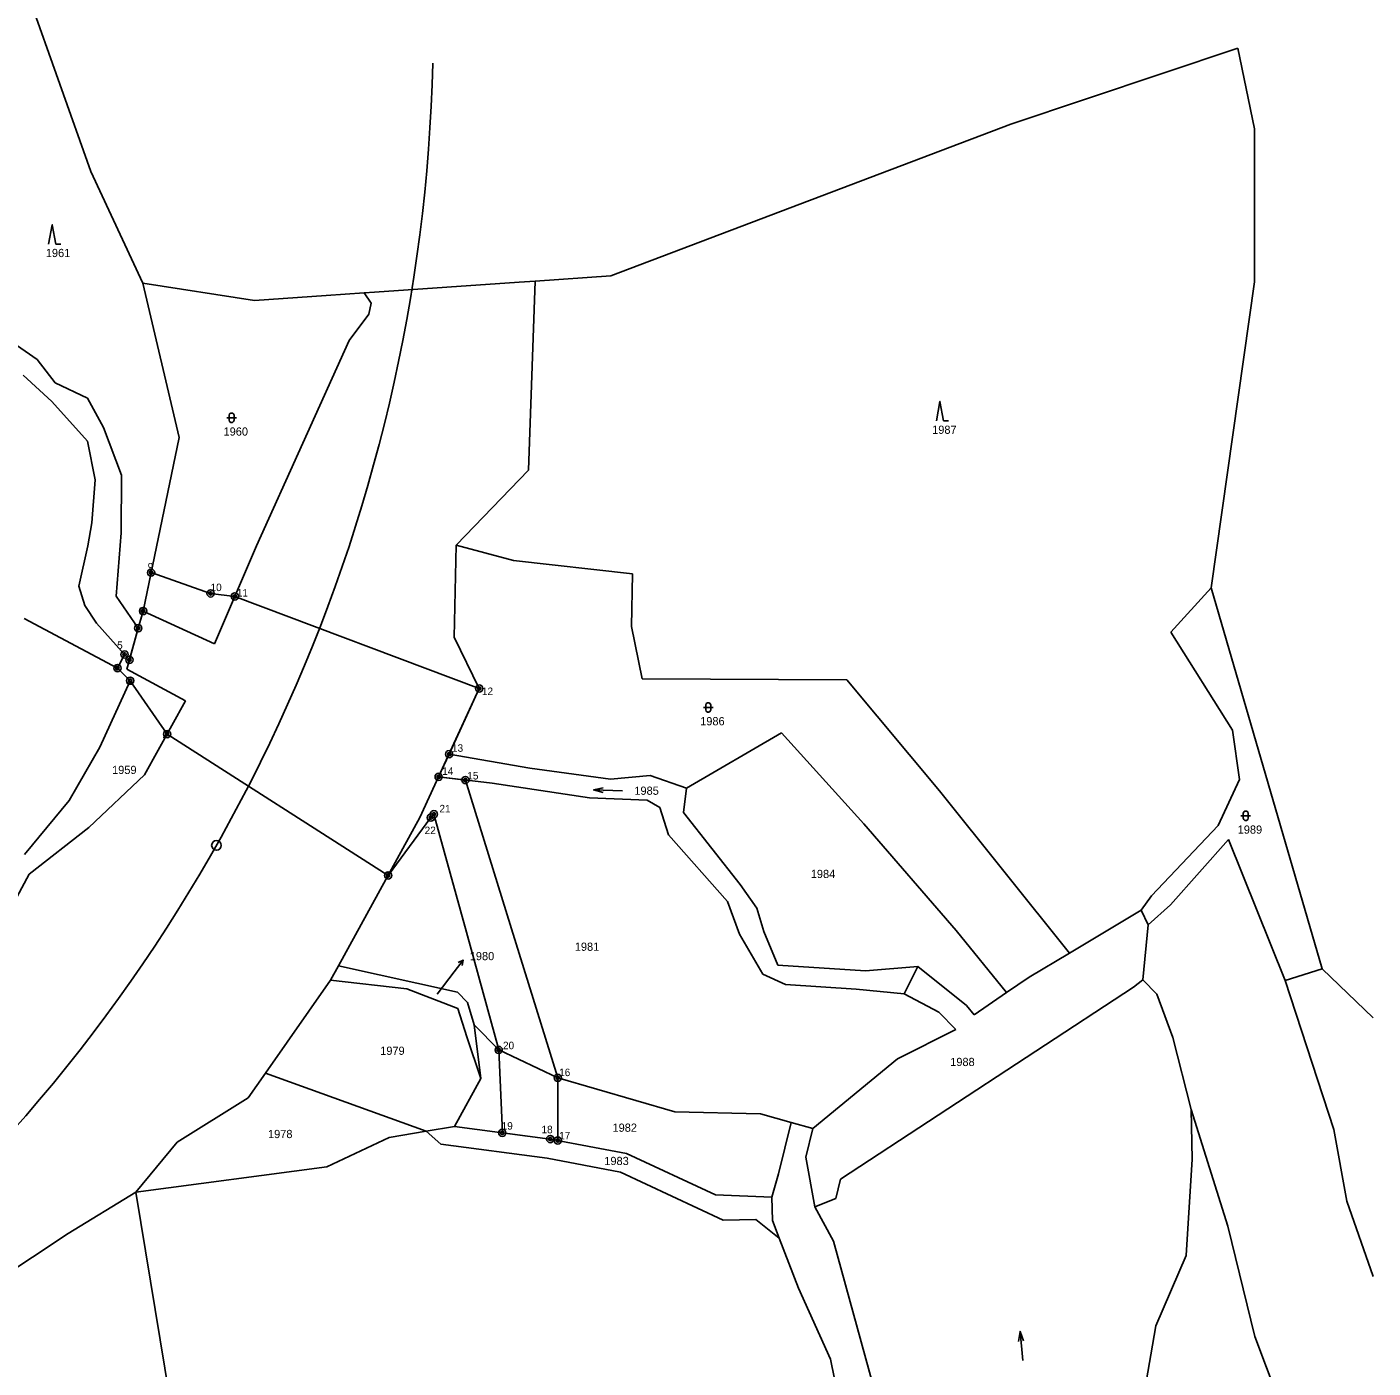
# Model space of a CAD drawing. Extents: x -801853 to -800578, y -1017479 to -1016338.
# Drawn here: x -801170.2 to -800891.7, y -1017184.4 to -1016906.9 of the extents above; entities that cross this region are included whole.
import ezdxf

# ---------------------------------------------------------------- set-up
doc = ezdxf.new("R2010")
doc.units = 0
for name, color, linetype in [('body', 7, 'Continuous'), ('cisla', 7, 'Continuous'), ('Default', 7, 'Continuous'), ('KN_HRANICE', 7, 'Continuous'), ('KN_KULTURY', 7, 'Continuous'), ('KN_PARCELY', 7, 'Continuous'), ('obvod_stavby', 7, 'Continuous'), ('Svršek_hkm_100', 7, 'Continuous'), ('Železniční svršek', 7, 'Continuous')]:
    doc.layers.add(name, color=color, linetype=linetype)

# ---------------------------------------------------------------- blocks, each defined once
blk = doc.blocks.new('308')
at = {"layer": 'Default'}
blk.add_lwpolyline([(-0.75, 0), (0, 4), (0.75, 0), (1.75, 0)], dxfattribs=at)
blk = doc.blocks.new('316')
at = {"layer": 'Default'}
for points in [[(-1, 1), (0.27, 1), (1, 1)], [(-0.5, 1.5), (-0.4, 1.79), (-0.15, 1.97), (0.16, 1.97), (0.41, 1.79), (0.51, 1.5), (0.51, 0.5), (0.41, 0.21), (0.16, 0.03), (-0.15, 0.03), (-0.4, 0.21), (-0.5, 0.5), (-0.5, 1.5)]]:
    blk.add_lwpolyline(points, dxfattribs=at)
blk = doc.blocks.new('802')
at = {"layer": 'Default'}
blk.add_line((-3, 0), (3, 0), dxfattribs=at)
blk.add_lwpolyline([(1, 0.5), (3, 0), (1, -0.5)], dxfattribs=at)
blk = doc.blocks.new('10292')
at = {"layer": 'Default'}
blk.add_line((0, 3), (0, 0), dxfattribs=at)
blk.add_lwpolyline([(-0.5, 2), (0, 3), (0.5, 2)], dxfattribs=at)

msp = doc.modelspace()

# ---------------------------------------------------------------- linework, layer by layer
at = {"layer": 'body'}
for p, q in [((-801144.52, -1017019.83), (-801144.52, -1017019.83)), ((-801132.21, -1017024.12), (-801132.21, -1017024.12)), ((-801127.2, -1017024.74), (-801127.2, -1017024.74)), ((-801146.17, -1017027.77), (-801146.17, -1017027.77)), ((-801147.17, -1017031.33), (-801147.17, -1017031.33)), ((-801150, -1017036.76), (-801150, -1017036.76)), ((-801151.48, -1017039.58), (-801151.48, -1017039.58)), ((-801149.01, -1017037.86), (-801149.01, -1017037.86)), ((-801148.85, -1017042.19), (-801148.85, -1017042.19)), ((-801076.63, -1017043.81), (-801076.63, -1017043.81)), ((-801141.22, -1017053.25), (-801141.22, -1017053.25)), ((-801082.88, -1017057.4), (-801082.88, -1017057.4)), ((-801085.03, -1017062.08), (-801085.03, -1017062.08)), ((-801079.49, -1017062.75), (-801079.49, -1017062.75)), ((-801086.64, -1017070.52), (-801086.64, -1017070.52)), ((-801086, -1017069.82), (-801086, -1017069.82)), ((-801095.48, -1017082.49), (-801095.48, -1017082.49)), ((-801072.61, -1017118.61), (-801072.61, -1017118.61)), ((-801060.39, -1017124.37), (-801060.39, -1017124.37)), ((-801071.86, -1017135.76), (-801071.86, -1017135.76)), ((-801061.94, -1017137.05), (-801061.94, -1017137.05)), ((-801060.39, -1017137.35), (-801060.39, -1017137.35))]:
    msp.add_line(p, q, dxfattribs=at)
for centre, radius in [((-801144.52, -1017019.83), 0.75), ((-801144.52, -1017019.83), 0.35), ((-801132.21, -1017024.12), 0.75), ((-801132.21, -1017024.12), 0.35), ((-801127.2, -1017024.74), 0.75), ((-801127.2, -1017024.74), 0.35), ((-801146.17, -1017027.77), 0.75), ((-801146.17, -1017027.77), 0.35), ((-801147.17, -1017031.33), 0.75), ((-801147.17, -1017031.33), 0.35), ((-801150, -1017036.76), 0.75), ((-801150, -1017036.76), 0.35), ((-801149.01, -1017037.86), 0.75), ((-801151.48, -1017039.58), 0.75), ((-801151.48, -1017039.58), 0.35), ((-801149.01, -1017037.86), 0.35), ((-801148.85, -1017042.19), 0.75), ((-801148.85, -1017042.19), 0.35), ((-801076.63, -1017043.81), 0.75), ((-801076.63, -1017043.81), 0.35), ((-801141.22, -1017053.25), 0.75), ((-801141.22, -1017053.25), 0.35), ((-801082.88, -1017057.4), 0.75), ((-801082.88, -1017057.4), 0.35), ((-801085.03, -1017062.08), 0.75), ((-801085.03, -1017062.08), 0.35), ((-801079.49, -1017062.75), 0.75), ((-801079.49, -1017062.75), 0.35), ((-801086.64, -1017070.52), 0.75), ((-801086.64, -1017070.52), 0.35), ((-801086, -1017069.82), 0.75), ((-801086, -1017069.82), 0.35), ((-801095.48, -1017082.49), 0.75), ((-801095.48, -1017082.49), 0.35), ((-801072.61, -1017118.61), 0.75), ((-801072.61, -1017118.61), 0.35), ((-801060.39, -1017124.37), 0.75), ((-801060.39, -1017124.37), 0.35), ((-801071.86, -1017135.76), 0.75), ((-801071.86, -1017135.76), 0.35), ((-801061.94, -1017137.05), 0.75), ((-801061.94, -1017137.05), 0.35), ((-801060.39, -1017137.35), 0.75), ((-801060.39, -1017137.35), 0.35)]:
    msp.add_circle(centre, radius, dxfattribs=at)
at = {"layer": 'KN_HRANICE'}
for p, q in [((-801173.56, -1016890), (-801157.02, -1016936.79)), ((-800966.67, -1016927.02), (-800919.72, -1016911.28)), ((-800919.72, -1016911.28), (-800916.22, -1016927.99)), ((-801049.4, -1016958.4), (-800966.67, -1016927.02)), ((-800916.22, -1016927.99), (-800916.27, -1016959.63)), ((-801157.02, -1016936.79), (-801146.24, -1016959.95)), ((-801068.35, -1016959.71), (-801065.05, -1016959.48)), ((-801066.45, -1016998.62), (-801065.05, -1016959.48)), ((-801065.05, -1016959.48), (-801049.4, -1016958.4)), ((-801138.7, -1016991.88), (-801146.24, -1016959.95)), ((-801146.24, -1016959.95), (-801123.1, -1016963.5)), ((-801108.28, -1016962.47), (-801100.45, -1016961.93)), ((-801100.45, -1016961.93), (-801098.33, -1016961.78)), ((-801099.01, -1016964.03), (-801100.45, -1016961.93)), ((-801098.33, -1016961.78), (-801068.35, -1016959.71)), ((-800916.27, -1016959.63), (-800925.21, -1017022.97)), ((-801123.1, -1016963.5), (-801108.28, -1016962.47)), ((-801099.44, -1016966.34), (-801099.01, -1016964.03)), ((-801103.54, -1016971.8), (-801099.44, -1016966.34)), ((-801168.07, -1016975.74), (-801173.07, -1016972.28)), ((-801122.73, -1017014.27), (-801103.54, -1016971.8)), ((-801164.36, -1016980.52), (-801168.07, -1016975.74)), ((-801165.08, -1016984.43), (-801171.01, -1016978.97)), ((-801157.66, -1016983.69), (-801164.36, -1016980.52)), ((-801157.69, -1016992.59), (-801165.08, -1016984.43)), ((-801154.36, -1016989.8), (-801157.66, -1016983.69)), ((-801150.62, -1016999.68), (-801154.36, -1016989.8)), ((-801156.11, -1017000.61), (-801157.69, -1016992.59)), ((-801146.17, -1017027.77), (-801138.7, -1016991.88)), ((-801156.79, -1017009.49), (-801156.11, -1017000.61)), ((-801150.74, -1017011.59), (-801150.62, -1016999.68)), ((-801081.43, -1017014.11), (-801066.45, -1016998.62)), ((-801156.79, -1017009.49), (-801157.64, -1017014.26)), ((-801151.72, -1017024.71), (-801150.74, -1017011.59)), ((-801159.44, -1017022.65), (-801157.64, -1017014.26)), ((-801131.4, -1017034.56), (-801122.73, -1017014.27)), ((-801081.81, -1017033.2), (-801081.43, -1017014.11)), ((-801081.43, -1017014.11), (-801069.54, -1017017.32)), ((-801069.54, -1017017.32), (-801044.91, -1017020.07)), ((-801044.91, -1017020.07), (-801045.15, -1017030.95)), ((-801159.44, -1017022.65), (-801158.23, -1017026.66)), ((-800933.53, -1017032.14), (-800925.21, -1017022.97)), ((-800925.21, -1017022.97), (-800922.04, -1017033.85)), ((-801147.17, -1017031.33), (-801151.72, -1017024.71)), ((-801158.23, -1017026.66), (-801155.85, -1017030.29)), ((-801147.17, -1017031.33), (-801146.17, -1017027.77)), ((-801146.17, -1017027.77), (-801131.4, -1017034.56)), ((-801170.76, -1017029.31), (-801151.48, -1017039.58)), ((-801150, -1017036.76), (-801155.85, -1017030.29)), ((-801148.65, -1017036.59), (-801147.17, -1017031.33)), ((-801045.15, -1017030.95), (-801042.92, -1017041.79)), ((-801076.63, -1017043.81), (-801081.81, -1017033.2)), ((-800920.82, -1017052.46), (-800933.53, -1017032.14)), ((-800922.04, -1017033.85), (-800902.21, -1017101.81)), ((-801150, -1017036.76), (-801151.48, -1017039.58)), ((-801150, -1017036.76), (-801149.01, -1017037.86)), ((-801149.01, -1017037.86), (-801148.65, -1017036.59)), ((-801151.48, -1017039.58), (-801148.85, -1017042.19)), ((-801149.55, -1017039.8), (-801149.01, -1017037.86)), ((-801137.41, -1017046.38), (-801149.55, -1017039.8)), ((-801155.16, -1017055.94), (-801148.85, -1017042.19)), ((-801042.92, -1017041.79), (-801000.61, -1017041.98)), ((-801000.61, -1017041.98), (-800981.44, -1017064.98)), ((-801082.88, -1017057.4), (-801076.63, -1017043.81)), ((-801145.88, -1017061.68), (-801137.41, -1017046.38)), ((-801014.12, -1017052.97), (-801033.76, -1017064.4)), ((-800997.04, -1017071.83), (-801014.12, -1017052.97)), ((-800919.32, -1017062.66), (-800920.82, -1017052.46)), ((-801161.48, -1017067), (-801155.16, -1017055.94)), ((-801082.88, -1017057.4), (-801085.03, -1017062.08)), ((-801066.15, -1017060.28), (-801082.88, -1017057.4)), ((-801157.42, -1017072.56), (-801145.88, -1017061.68)), ((-801088.9, -1017070.5), (-801085.03, -1017062.08)), ((-801085.03, -1017062.08), (-801073.95, -1017063.41)), ((-801049.51, -1017062.6), (-801066.15, -1017060.28)), ((-801041.29, -1017061.79), (-801049.51, -1017062.6)), ((-801033.76, -1017064.4), (-801041.29, -1017061.79)), ((-801073.95, -1017063.41), (-801053.83, -1017066.4)), ((-801033.76, -1017064.4), (-801034.38, -1017069.49)), ((-800981.44, -1017064.98), (-800954.55, -1017098.59)), ((-800923.75, -1017072.16), (-800919.32, -1017062.66)), ((-801170.68, -1017078.19), (-801161.48, -1017067)), ((-801053.83, -1017066.4), (-801041.9, -1017066.94)), ((-801041.9, -1017066.94), (-801039.25, -1017068.41)), ((-801105.75, -1017101.2), (-801088.9, -1017070.5)), ((-801039.25, -1017068.41), (-801037.51, -1017074.11)), ((-801034.38, -1017069.49), (-801022.63, -1017084.37)), ((-801169.74, -1017082.25), (-801157.42, -1017072.56)), ((-800977.94, -1017093.89), (-800997.04, -1017071.83)), ((-800937.55, -1017086.7), (-800923.75, -1017072.16)), ((-801037.51, -1017074.11), (-801025.28, -1017087.9)), ((-800933.62, -1017088.6), (-800921.62, -1017075.06)), ((-800921.62, -1017075.06), (-800909.89, -1017104.24)), ((-801179.48, -1017100.28), (-801169.74, -1017082.25)), ((-801022.63, -1017084.37), (-801019.21, -1017089.27)), ((-800939.68, -1017089.67), (-800937.55, -1017086.7)), ((-801025.28, -1017087.9), (-801022.81, -1017094.66)), ((-801019.21, -1017089.27), (-801017.73, -1017094.07)), ((-800954.55, -1017098.59), (-800939.68, -1017089.67)), ((-800939.68, -1017089.67), (-800938.24, -1017092.74)), ((-800938.24, -1017092.74), (-800933.62, -1017088.6)), ((-800938.24, -1017092.74), (-800939.36, -1017104.09)), ((-801022.81, -1017094.66), (-801017.99, -1017102.9)), ((-801017.73, -1017094.07), (-801014.89, -1017101.06)), ((-800967.52, -1017106.74), (-800977.94, -1017093.89)), ((-800962.84, -1017103.56), (-800954.55, -1017098.59)), ((-801107.38, -1017104.16), (-801105.75, -1017101.2)), ((-801081.11, -1017106.63), (-801105.75, -1017101.2)), ((-801014.89, -1017101.06), (-800996.7, -1017102.24)), ((-800996.7, -1017102.24), (-800985.89, -1017101.36)), ((-800988.75, -1017106.97), (-800985.89, -1017101.36)), ((-800985.89, -1017101.36), (-800975.8, -1017109.4)), ((-801107.38, -1017104.16), (-801120.85, -1017123.38)), ((-801091.59, -1017105.94), (-801107.38, -1017104.16)), ((-801017.99, -1017102.9), (-801013.25, -1017105.09)), ((-800967.52, -1017106.74), (-800962.84, -1017103.56)), ((-800939.36, -1017104.09), (-800941.26, -1017105.59)), ((-800936.45, -1017107.04), (-800939.36, -1017104.09)), ((-800909.89, -1017104.24), (-800902.21, -1017101.81)), ((-800909.89, -1017104.24), (-800899.86, -1017135.06)), ((-800902.21, -1017101.81), (-800891.71, -1017111.95)), ((-801081.08, -1017110), (-801091.59, -1017105.94)), ((-801079.03, -1017108.8), (-801081.11, -1017106.63)), ((-801013.25, -1017105.09), (-800998.64, -1017106.06)), ((-800941.26, -1017105.59), (-801001.86, -1017145.37)), ((-800998.64, -1017106.06), (-800988.75, -1017106.97)), ((-800988.75, -1017106.97), (-800981.55, -1017110.76)), ((-800974.27, -1017111.32), (-800967.52, -1017106.74)), ((-800933.11, -1017116.01), (-800936.45, -1017107.04)), ((-801077.69, -1017113.44), (-801079.03, -1017108.8)), ((-800975.8, -1017109.4), (-800974.27, -1017111.32)), ((-801079.17, -1017115.86), (-801081.08, -1017110)), ((-800981.55, -1017110.76), (-800978.03, -1017114.36)), ((-801076.29, -1017124.55), (-801077.69, -1017113.44)), ((-801072.61, -1017118.61), (-801077.69, -1017113.44)), ((-800978.03, -1017114.36), (-800990.08, -1017120.48)), ((-801076.29, -1017124.55), (-801079.17, -1017115.86)), ((-800929.36, -1017130.92), (-800933.11, -1017116.01)), ((-801060.39, -1017124.37), (-801072.61, -1017118.61)), ((-800990.08, -1017120.48), (-801007.59, -1017134.85)), ((-801120.85, -1017123.38), (-801124.46, -1017128.53)), ((-801120.85, -1017123.38), (-801087.64, -1017135.44)), ((-801081.77, -1017134.46), (-801076.29, -1017124.55)), ((-801036.16, -1017131.43), (-801060.39, -1017124.37)), ((-801124.46, -1017128.53), (-801139.16, -1017137.71)), ((-801018.45, -1017131.86), (-801036.16, -1017131.43)), ((-801012.13, -1017133.6), (-801018.45, -1017131.86)), ((-800921.75, -1017155.11), (-800929.36, -1017130.92)), ((-800929.15, -1017141.22), (-800929.36, -1017130.92)), ((-801087.64, -1017135.44), (-801081.77, -1017134.46)), ((-801081.77, -1017134.46), (-801061.94, -1017137.05)), ((-801014.73, -1017144.22), (-801012.13, -1017133.6)), ((-801007.59, -1017134.85), (-801012.13, -1017133.6)), ((-801009.05, -1017140.81), (-801007.59, -1017134.85)), ((-801139.16, -1017137.71), (-801147.67, -1017148.04)), ((-801095.3, -1017136.72), (-801108.14, -1017142.81)), ((-801095.3, -1017136.72), (-801087.64, -1017135.44)), ((-801087.64, -1017135.44), (-801084.58, -1017138.12)), ((-801061.94, -1017137.05), (-801046.19, -1017140.07)), ((-800899.86, -1017135.06), (-800897.14, -1017149.92)), ((-801084.58, -1017138.12), (-801062.58, -1017141)), ((-801046.19, -1017140.07), (-801027.73, -1017148.59)), ((-801108.14, -1017142.81), (-801147.67, -1017148.04)), ((-801062.58, -1017141), (-801047.43, -1017143.9)), ((-801007.17, -1017151.05), (-801009.05, -1017140.81)), ((-800930.37, -1017161.16), (-800929.15, -1017141.22)), ((-801047.43, -1017143.9), (-801026.14, -1017153.86)), ((-801014.73, -1017144.22), (-801016.11, -1017149.08)), ((-801001.86, -1017145.37), (-801002.87, -1017149.33)), ((-801147.67, -1017148.04), (-801161.67, -1017156.6)), ((-801147.67, -1017148.04), (-801120.7, -1017312.51)), ((-801027.73, -1017148.59), (-801016.11, -1017149.08)), ((-801016.11, -1017149.08), (-801015.97, -1017153.92)), ((-801002.87, -1017149.33), (-801007.17, -1017151.05)), ((-801007.17, -1017151.05), (-801003.34, -1017158.2)), ((-800897.14, -1017149.92), (-800891.71, -1017165.48)), ((-801026.14, -1017153.86), (-801019.43, -1017153.68)), ((-801019.43, -1017153.68), (-801014.57, -1017157.55)), ((-801015.97, -1017153.92), (-801014.57, -1017157.55)), ((-801161.67, -1017156.6), (-801192.33, -1017176.83)), ((-800916.2, -1017177.92), (-800921.75, -1017155.11)), ((-801014.57, -1017157.55), (-801010.59, -1017167.92)), ((-801003.34, -1017158.2), (-800995.15, -1017188.06)), ((-800936.68, -1017175.71), (-800930.37, -1017161.16)), ((-801010.59, -1017167.92), (-801003.97, -1017182.58)), ((-800939.01, -1017189.32), (-800936.68, -1017175.71)), ((-800904.03, -1017209.93), (-800916.2, -1017177.92)), ((-801003.97, -1017182.58), (-800982.5, -1017289.15))]:
    msp.add_line(p, q, dxfattribs=at)
at = {"layer": 'KN_PARCELY'}
msp.add_line((-801085.34, -1017107.05), (-801081.8, -1017102.41), dxfattribs=at)
at = {"layer": 'obvod_stavby'}
for points in [[(-801141.22, -1017053.25), (-801148.85, -1017042.19), (-801151.48, -1017039.58), (-801150, -1017036.76), (-801149.01, -1017037.86), (-801147.17, -1017031.33), (-801146.17, -1017027.77), (-801144.52, -1017019.83), (-801132.21, -1017024.12), (-801127.2, -1017024.74), (-801076.63, -1017043.81), (-801085.03, -1017062.08), (-801079.49, -1017062.75), (-801069.94, -1017093.56), (-801060.39, -1017124.37), (-801060.39, -1017137.35), (-801061.94, -1017137.05), (-801071.85, -1017135.76), (-801072.61, -1017118.61), (-801079.3, -1017094.22), (-801086, -1017069.82), (-801086.64, -1017070.52), (-801095.48, -1017082.49)], [(-801086, -1017069.82), (-801086.64, -1017070.52), (-801095.48, -1017082.49), (-801141.22, -1017053.25), (-801148.85, -1017042.19), (-801151.48, -1017039.58)]]:
    msp.add_lwpolyline(points, dxfattribs=at)
at = {"layer": 'Svršek_hkm_100'}
msp.add_circle((-801130.99, -1017076.27), 1, dxfattribs=at)
at = {"layer": 'Železniční svršek'}
msp.add_arc((-801431.93, -1016905.94), 345.8, 311.7457, 358.6036, dxfattribs=at)

# ---------------------------------------------------------------- block references
at = {"layer": 'KN_KULTURY'}
for name, p in [('308', (-801164.97, -1016951.82)), ('308', (-800981.31, -1016988.4)), ('316', (-801127.87, -1016988.77)), ('316', (-801029.26, -1017048.72)), ('316', (-800918.06, -1017071.15))]:
    msp.add_blockref(name, p, dxfattribs=at)
for p, rotation in [((-801049.99, -1017064.88), 178.24716999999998), ((-800964.44, -1017179.86), 95.512064)]:
    msp.add_blockref('802', p, dxfattribs=dict(at, rotation=rotation))
at = {"layer": 'KN_PARCELY', "rotation": -37.367466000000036}
msp.add_blockref('10292', (-801081.8, -1017102.41), dxfattribs=at)

# ---------------------------------------------------------------- texts
at = {"layer": 'cisla'}
for s, p in [('  9', (-801146.38, -1017019.38)), (' 10', (-801132.8, -1017023.65)), (' 11', (-801127.36, -1017024.79)), ('  8', (-801148.24, -1017028.55)), ('  7', (-801149.24, -1017032.11)), ('  5', (-801152.7, -1017035.61)), ('  6', (-801151.08, -1017038.64)), ('  4', (-801153.55, -1017040.36)), ('  3', (-801150.92, -1017042.97)), (' 12', (-801076.66, -1017045.16)), ('  2', (-801143.29, -1017054.03)), (' 13', (-801082.85, -1017056.9)), (' 14', (-801084.89, -1017061.69)), (' 15', (-801079.68, -1017062.63)), ('21', (-801084.87, -1017069.44)), ('22', (-801087.93, -1017073.94)), ('  1', (-801097.29, -1017083.27)), ('20', (-801071.72, -1017118.46)), (' 16', (-801060.68, -1017124.03)), (' 19', (-801072.58, -1017135.1)), (' 18', (-801064.33, -1017135.85)), (' 17', (-801060.68, -1017137.12))]:
    msp.add_text(s, height=1.552, dxfattribs=at).set_placement(p)
at = {"layer": 'KN_PARCELY'}
for s, height, p in [('1961', 1.7, (-801166.3, -1016954.52)), ('1960', 1.7, (-801129.53, -1016991.47)), ('1987', 1.7, (-800982.93, -1016991.1)), ('1986', 1.7, (-801030.92, -1017051.42)), ('1959', 1.7, (-801152.59, -1017061.5)), ('1985', 1.7, (-801044.54, -1017065.8)), ('1989', 1.7, (-800919.72, -1017073.85)), ('1984', 1.7, (-801008.04, -1017083.03)), ('1980', 1.7, (-801078.59, -1017100.03)), ('1981', 1.7, (-801056.86, -1017098.09)), ('1980', 0.1, (-801085.32, -1017107.05)), ('1979', 1.7, (-801097.12, -1017119.62)), ('1988', 1.7, (-800979.19, -1017121.94)), ('1982', 1.7, (-801049.06, -1017135.54)), ('1978', 1.7, (-801120.33, -1017136.85)), ('1983', 1.7, (-801050.76, -1017142.43))]:
    msp.add_text(s, height=height, dxfattribs=at).set_placement(p)

doc.saveas('drawing.dxf')
